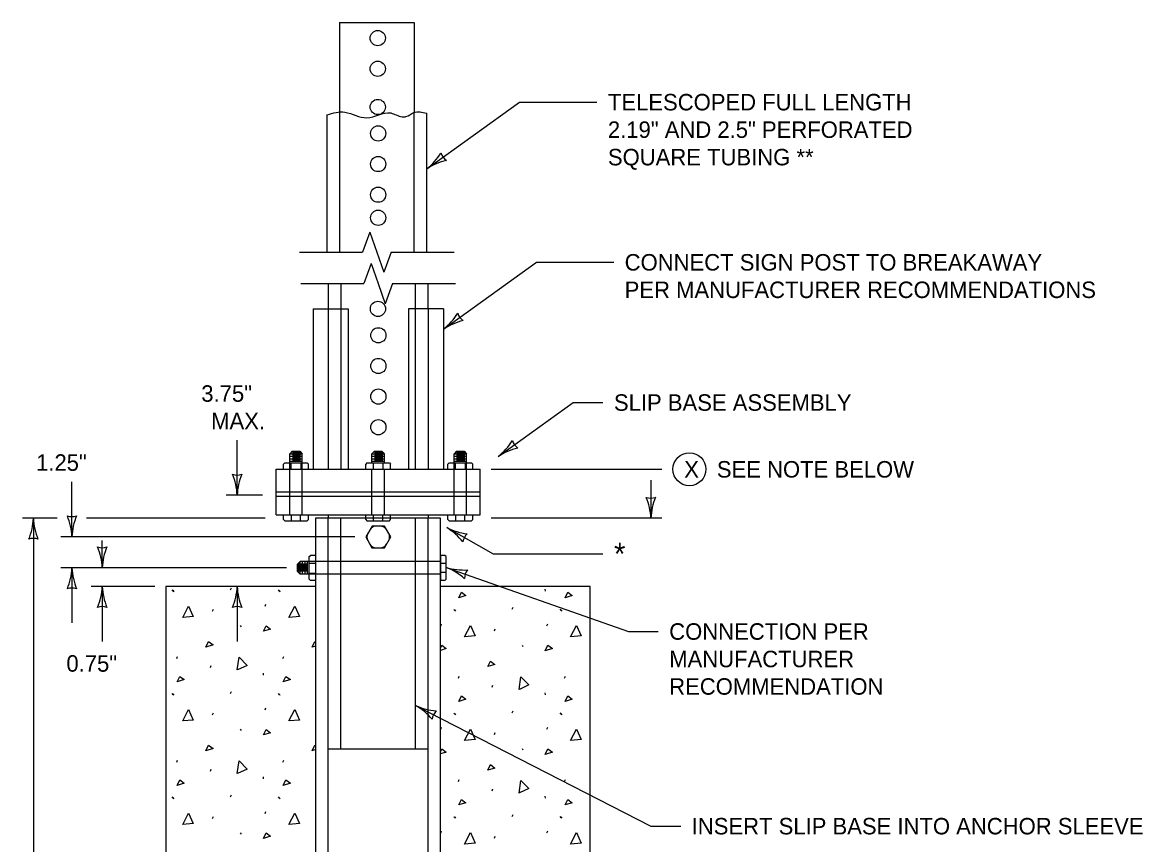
# Model space of a CAD drawing. Extents: x 49940 to 50043, y 49986 to 50011.
# Drawn here: x 49951.371 to 49955.45, y 49994.357 to 49997.349 of the extents above; entities that cross this region are included whole.
import ezdxf

# ---------------------------------------------------------------- set-up
doc = ezdxf.new("R2010")
doc.units = 0
for name, color, linetype in [('Level 1', 7, 'Continuous'), ('Level 2', 7, 'Continuous'), ('Level 3', 7, 'Continuous'), ('Level 4', 7, 'Continuous'), ('Level 6', 7, 'Continuous')]:
    doc.layers.add(name, color=color, linetype=linetype)

msp = doc.modelspace()

# ---------------------------------------------------------------- linework, layer by layer
at = {"layer": 'Level 1'}
for p, q in [((49952.5255, 49997.3494), (49952.798, 49997.3494)), ((49952.4305, 49996.3076), (49952.4305, 49995.7231)), ((49952.4305, 49996.3076), (49952.5577, 49996.3076)), ((49952.5577, 49996.3076), (49952.5577, 49995.7231)), ((49952.7772, 49996.3076), (49952.7772, 49995.7231)), ((49952.9044, 49996.3076), (49952.7772, 49996.3076)), ((49952.9044, 49996.3076), (49952.9044, 49995.7231)), ((49952.3541, 49995.7888), (49952.345, 49995.7798)), ((49952.345, 49995.7466), (49952.345, 49995.7798)), ((49952.345, 49995.7798), (49952.3904, 49995.7798)), ((49952.3541, 49995.7888), (49952.3813, 49995.7888)), ((49952.3542, 49995.7844), (49952.3841, 49995.7844)), ((49952.3542, 49995.7753), (49952.3841, 49995.7753)), ((49952.3813, 49995.7888), (49952.3904, 49995.7798)), ((49952.3904, 49995.7466), (49952.3904, 49995.7798)), ((49952.6531, 49995.7888), (49952.644, 49995.7798)), ((49952.644, 49995.7466), (49952.644, 49995.7798)), ((49952.644, 49995.7798), (49952.6895, 49995.7798)), ((49952.6531, 49995.7888), (49952.6804, 49995.7888)), ((49952.6533, 49995.7844), (49952.6832, 49995.7844)), ((49952.6533, 49995.7753), (49952.6832, 49995.7753)), ((49952.6804, 49995.7888), (49952.6895, 49995.7798)), ((49952.6895, 49995.7466), (49952.6895, 49995.7798)), ((49952.9522, 49995.7888), (49952.9431, 49995.7798)), ((49952.9431, 49995.7466), (49952.9431, 49995.7798)), ((49952.9431, 49995.7798), (49952.9885, 49995.7798)), ((49952.9522, 49995.7888), (49952.9794, 49995.7888)), ((49952.9523, 49995.7844), (49952.9822, 49995.7844)), ((49952.9523, 49995.7753), (49952.9822, 49995.7753)), ((49952.9794, 49995.7888), (49952.9885, 49995.7798)), ((49952.9885, 49995.7466), (49952.9885, 49995.7798)), ((49952.3267, 49995.7466), (49952.3223, 49995.742)), ((49952.3223, 49995.7231), (49952.3223, 49995.742)), ((49952.3267, 49995.7466), (49952.4086, 49995.7466)), ((49952.345, 49995.7708), (49952.3904, 49995.7708)), ((49952.345, 49995.7616), (49952.3904, 49995.7616)), ((49952.345, 49995.7526), (49952.3904, 49995.7526)), ((49952.3489, 49995.7466), (49952.3489, 49995.7242)), ((49952.3542, 49995.7662), (49952.3841, 49995.7662)), ((49952.3542, 49995.7571), (49952.3841, 49995.7571)), ((49952.3851, 49995.7466), (49952.3851, 49995.7242)), ((49952.4086, 49995.7466), (49952.4132, 49995.742)), ((49952.4132, 49995.7231), (49952.4132, 49995.742)), ((49952.6258, 49995.7466), (49952.6212, 49995.742)), ((49952.6212, 49995.7231), (49952.6212, 49995.742)), ((49952.6258, 49995.7466), (49952.7076, 49995.7466)), ((49952.644, 49995.7708), (49952.6895, 49995.7708)), ((49952.644, 49995.7616), (49952.6895, 49995.7616)), ((49952.644, 49995.7526), (49952.6895, 49995.7526)), ((49952.6481, 49995.7466), (49952.6481, 49995.7242)), ((49952.6533, 49995.7662), (49952.6832, 49995.7662)), ((49952.6533, 49995.7571), (49952.6832, 49995.7571)), ((49952.6841, 49995.7466), (49952.6841, 49995.7242)), ((49952.7076, 49995.7466), (49952.7121, 49995.742)), ((49952.7121, 49995.7231), (49952.7121, 49995.742)), ((49952.9249, 49995.7466), (49952.9203, 49995.742)), ((49952.9203, 49995.7231), (49952.9203, 49995.742)), ((49952.9249, 49995.7466), (49953.0067, 49995.7466)), ((49952.9431, 49995.7708), (49952.9885, 49995.7708)), ((49952.9431, 49995.7616), (49952.9885, 49995.7616)), ((49952.9431, 49995.7526), (49952.9885, 49995.7526)), ((49952.947, 49995.7466), (49952.947, 49995.7242)), ((49952.9523, 49995.7662), (49952.9822, 49995.7662)), ((49952.9523, 49995.7571), (49952.9822, 49995.7571)), ((49952.9832, 49995.7466), (49952.9832, 49995.7242)), ((49953.0067, 49995.7466), (49953.0112, 49995.742)), ((49953.0112, 49995.7231), (49953.0112, 49995.742)), ((49952.295, 49995.5571), (49952.295, 49995.7231)), ((49952.295, 49995.7231), (49952.644, 49995.7231)), ((49952.644, 49995.5571), (49952.644, 49995.7231)), ((49952.644, 49995.7231), (49952.6895, 49995.7231)), ((49952.6895, 49995.5571), (49952.6895, 49995.7231)), ((49952.6895, 49995.7231), (49953.0385, 49995.7231)), ((49953.0385, 49995.5571), (49953.0385, 49995.7231)), ((49952.295, 49995.6406), (49953.0385, 49995.6406)), ((49952.295, 49995.6257), (49953.0385, 49995.6257)), ((49952.295, 49995.5571), (49952.644, 49995.5571)), ((49952.3223, 49995.5404), (49952.3223, 49995.5571)), ((49952.3223, 49995.5404), (49952.3267, 49995.536)), ((49952.3267, 49995.536), (49952.4086, 49995.536)), ((49952.351, 49995.536), (49952.351, 49995.5566)), ((49952.3841, 49995.536), (49952.3841, 49995.5566)), ((49952.4086, 49995.536), (49952.4132, 49995.5404)), ((49952.4132, 49995.5404), (49952.4132, 49995.5571)), ((49952.4851, 49995.5571), (49952.4851, 49995.5448)), ((49952.6212, 49995.5404), (49952.6212, 49995.5571)), ((49952.6212, 49995.5404), (49952.6258, 49995.536)), ((49952.6258, 49995.536), (49952.7076, 49995.536)), ((49952.644, 49995.5571), (49952.6895, 49995.5571)), ((49952.6501, 49995.536), (49952.6501, 49995.5566)), ((49952.6832, 49995.536), (49952.6832, 49995.5566)), ((49952.6895, 49995.5571), (49953.0385, 49995.5571)), ((49952.7076, 49995.536), (49952.7121, 49995.5404)), ((49952.7121, 49995.5404), (49952.7121, 49995.5571)), ((49952.8484, 49995.5571), (49952.8484, 49995.5448)), ((49952.9203, 49995.5404), (49952.9203, 49995.5571)), ((49952.9203, 49995.5404), (49952.9249, 49995.536)), ((49952.9249, 49995.536), (49953.0067, 49995.536)), ((49952.9491, 49995.536), (49952.9491, 49995.5566)), ((49952.9822, 49995.536), (49952.9822, 49995.5566)), ((49953.0067, 49995.536), (49953.0112, 49995.5404)), ((49953.0112, 49995.5404), (49953.0112, 49995.5571)), ((49952.4154, 49995.4054), (49952.4201, 49995.41)), ((49952.4154, 49995.3236), (49952.4154, 49995.4054)), ((49952.439, 49995.41), (49952.4201, 49995.41)), ((49952.91, 49995.41), (49952.8933, 49995.41)), ((49952.8933, 49995.41), (49952.8933, 49995.319)), ((49952.9146, 49995.4054), (49952.91, 49995.41)), ((49952.9146, 49995.3236), (49952.9146, 49995.4054)), ((49952.3731, 49995.3782), (49952.3822, 49995.3872)), ((49952.3731, 49995.3508), (49952.3731, 49995.3782)), ((49952.3777, 49995.3511), (49952.3777, 49995.3809)), ((49952.4154, 49995.3872), (49952.3822, 49995.3872)), ((49952.3822, 49995.3418), (49952.3822, 49995.3872)), ((49952.3867, 49995.3511), (49952.3867, 49995.3809)), ((49952.3913, 49995.3418), (49952.3913, 49995.3872)), ((49952.3959, 49995.3511), (49952.3959, 49995.3809)), ((49952.4004, 49995.3418), (49952.4004, 49995.3872)), ((49952.4051, 49995.3511), (49952.4051, 49995.3809)), ((49952.4095, 49995.3418), (49952.4095, 49995.3872)), ((49952.4154, 49995.382), (49952.439, 49995.382)), ((49952.9146, 49995.3809), (49952.8939, 49995.3809)), ((49952.3731, 49995.3508), (49952.3822, 49995.3418)), ((49952.4154, 49995.3418), (49952.3822, 49995.3418)), ((49952.4154, 49995.3457), (49952.439, 49995.3457)), ((49952.9146, 49995.3478), (49952.8939, 49995.3478)), ((49952.439, 49995.2968), (49951.8937, 49995.2968)), ((49951.8937, 49995.2968), (49951.8937, 49992.5705)), ((49951.916, 49995.2847), (49951.9193, 49995.2798)), ((49952.129, 49995.2847), (49952.1323, 49995.292)), ((49952.3025, 49995.2847), (49952.3059, 49995.2798)), ((49952.4154, 49995.3236), (49952.4201, 49995.319)), ((49952.439, 49995.319), (49952.4201, 49995.319)), ((49952.91, 49995.319), (49952.8933, 49995.319)), ((49953.4386, 49995.2968), (49952.8933, 49995.2968)), ((49952.91, 49995.319), (49952.9146, 49995.3236)), ((49953.2735, 49995.287), (49953.2742, 49995.2798)), ((49953.4386, 49992.5705), (49953.4386, 49995.2968)), ((49951.9193, 49995.2828), (49951.9226, 49995.2778)), ((49952.3059, 49995.2828), (49952.3091, 49995.2778)), ((49952.0637, 49995.2063), (49952.067, 49995.2136)), ((49952.2549, 49995.2248), (49952.2582, 49995.2321)), ((49952.942, 49995.2138), (49952.9452, 49995.2088)), ((49952.9452, 49995.212), (49952.9484, 49995.207)), ((49953.155, 49995.2138), (49953.1583, 49995.221)), ((49953.3285, 49995.2138), (49953.3317, 49995.2088)), ((49953.3317, 49995.212), (49953.335, 49995.207)), ((49952.8945, 49995.1539), (49952.8975, 49995.1612)), ((49953.2808, 49995.1539), (49953.2841, 49995.1612)), ((49952.1647, 49995.1545), (49952.1679, 49995.1497)), ((49953.0897, 49995.1352), (49953.0928, 49995.1426)), ((49953.1906, 49995.0837), (49953.1937, 49995.0788)), ((49951.933, 49995.0343), (49951.9362, 49995.0416)), ((49952.3195, 49995.0343), (49952.3228, 49995.0416)), ((49952.0557, 49995.0013), (49952.0588, 49995.0086)), ((49952.2475, 49994.981), (49952.2482, 49994.9737)), ((49952.959, 49994.9634), (49952.9622, 49994.9707)), ((49953.3455, 49994.9634), (49953.3488, 49994.9707)), ((49953.0816, 49994.9303), (49953.0847, 49994.9375)), ((49951.916, 49994.9077), (49951.9193, 49994.9027)), ((49951.9193, 49994.9059), (49951.9226, 49994.901)), ((49952.129, 49994.9077), (49952.1323, 49994.9149)), ((49952.3025, 49994.9077), (49952.3059, 49994.9027)), ((49952.3059, 49994.9059), (49952.3091, 49994.901)), ((49953.2735, 49994.9101), (49953.2742, 49994.9027)), ((49952.0637, 49994.8293), (49952.067, 49994.8366)), ((49952.2549, 49994.8478), (49952.2582, 49994.8551)), ((49952.942, 49994.8366), (49952.9452, 49994.8319)), ((49952.9452, 49994.8348), (49952.9484, 49994.83)), ((49953.155, 49994.8366), (49953.1583, 49994.8441)), ((49953.3285, 49994.8366), (49953.3317, 49994.8319)), ((49953.3317, 49994.8348), (49953.335, 49994.83)), ((49952.1647, 49994.7776), (49952.1679, 49994.7728)), ((49952.8945, 49994.7769), (49952.8975, 49994.7842)), ((49953.0897, 49994.7584), (49953.0928, 49994.7656)), ((49953.2808, 49994.7769), (49953.2841, 49994.7842)), ((49953.1906, 49994.7067), (49953.1937, 49994.7018)), ((49951.933, 49994.6573), (49951.9362, 49994.6646)), ((49952.0557, 49994.6242), (49952.0588, 49994.6316)), ((49952.3195, 49994.6573), (49952.3228, 49994.6646)), ((49952.2475, 49994.604), (49952.2482, 49994.5967)), ((49952.959, 49994.5864), (49952.9622, 49994.5937)), ((49953.3455, 49994.5864), (49953.3488, 49994.5937)), ((49953.0816, 49994.5534), (49953.0847, 49994.5606)), ((49951.916, 49994.5306), (49951.9193, 49994.5259)), ((49951.9193, 49994.5288), (49951.9226, 49994.5241)), ((49952.129, 49994.5306), (49952.1323, 49994.538)), ((49952.3025, 49994.5306), (49952.3059, 49994.5259)), ((49952.3059, 49994.5288), (49952.3091, 49994.5241)), ((49953.2735, 49994.5333), (49953.2742, 49994.5259)), ((49952.2549, 49994.4709), (49952.2582, 49994.4781)), ((49952.0637, 49994.4523), (49952.067, 49994.4596)), ((49952.942, 49994.4598), (49952.9452, 49994.4549)), ((49952.9452, 49994.4579), (49952.9484, 49994.4531)), ((49953.155, 49994.4598), (49953.1583, 49994.467)), ((49953.3285, 49994.4598), (49953.3317, 49994.4549)), ((49953.3317, 49994.4579), (49953.335, 49994.4531)), ((49952.1647, 49994.4007), (49952.1679, 49994.3958)), ((49952.8945, 49994.3999), (49952.8975, 49994.4072)), ((49953.0897, 49994.3813), (49953.0928, 49994.3886)), ((49953.2808, 49994.3999), (49953.2841, 49994.4072))]:
    msp.add_line(p, q, dxfattribs=at)
for points in [[(49952.5255, 49997.3494), (49952.5255, 49997.02)], [(49952.798, 49997.3494), (49952.7981, 49997.0215)], [(49952.4801, 49997.0145), (49952.4803, 49996.5136)], [(49952.8434, 49996.5137), (49952.8434, 49997.0186)], [(49952.4851, 49996.3989), (49952.4851, 49996.3076)], [(49952.8483, 49996.3076), (49952.8483, 49996.3989)], [(49952.8933, 49992.7115), (49952.8933, 49995.5448), (49952.439, 49995.5448), (49952.439, 49992.7115)], [(49952.9605, 49995.2556), (49952.9701, 49995.2758), (49952.9864, 49995.2636), (49952.9605, 49995.2556)], [(49953.3471, 49995.2556), (49953.3568, 49995.2758), (49953.3729, 49995.2636), (49953.3471, 49995.2556)], [(49951.9549, 49995.1844), (49951.9766, 49995.2256), (49951.9936, 49995.1876), (49951.9556, 49995.1844)], [(49952.3413, 49995.1844), (49952.3632, 49995.2256), (49952.38, 49995.1876), (49952.3421, 49995.1844)], [(49952.2493, 49995.1336), (49952.259, 49995.1538), (49952.2751, 49995.1417), (49952.2493, 49995.1336)], [(49952.9807, 49995.1136), (49953.0025, 49995.1546), (49953.0194, 49995.1167), (49952.9814, 49995.1136)], [(49953.3673, 49995.1136), (49953.3891, 49995.1546), (49953.406, 49995.1167), (49953.3681, 49995.1136)], [(49952.0396, 49995.0759), (49952.0494, 49995.0959), (49952.0655, 49995.0839), (49952.0396, 49995.0759)], [(49952.4263, 49995.0759), (49952.4359, 49995.0959), (49952.439, 49995.0938)], [(49952.439, 49995.0798), (49952.4263, 49995.0759)], [(49952.8933, 49995.0724), (49952.8983, 49995.0829), (49952.9145, 49995.0707), (49952.8933, 49995.0642)], [(49953.2753, 49995.0628), (49953.2849, 49995.0829), (49953.3011, 49995.0707), (49953.2753, 49995.0628)], [(49952.1538, 49994.993), (49952.1603, 49995.0391), (49952.1891, 49995.0092), (49952.1546, 49994.9932)], [(49953.0656, 49995.005), (49953.0753, 49995.0252), (49953.0914, 49995.013), (49953.0656, 49995.005)], [(49951.9346, 49994.9496), (49951.9443, 49994.9697), (49951.9604, 49994.9577), (49951.9346, 49994.9496)], [(49952.3212, 49994.9496), (49952.331, 49994.9697), (49952.3469, 49994.9577), (49952.3212, 49994.9496)], [(49953.1798, 49994.922), (49953.1862, 49994.968), (49953.2151, 49994.9384), (49953.1807, 49994.9222)], [(49952.9605, 49994.8787), (49952.9701, 49994.8989), (49952.9864, 49994.8867), (49952.9605, 49994.8787)], [(49953.3471, 49994.8787), (49953.3568, 49994.8989), (49953.3729, 49994.8867), (49953.3471, 49994.8787)], [(49951.9549, 49994.8075), (49951.9766, 49994.8486), (49951.9936, 49994.8107), (49951.9556, 49994.8075)], [(49952.3413, 49994.8075), (49952.3632, 49994.8486), (49952.38, 49994.8107), (49952.3421, 49994.8075)], [(49952.2493, 49994.7566), (49952.259, 49994.7767), (49952.2751, 49994.7647), (49952.2493, 49994.7566)], [(49952.9807, 49994.7366), (49953.0025, 49994.7778), (49953.0194, 49994.7397), (49952.9814, 49994.7366)], [(49953.3673, 49994.7366), (49953.3891, 49994.7778), (49953.406, 49994.7397), (49953.3681, 49994.7366)], [(49952.0396, 49994.6989), (49952.0494, 49994.7191), (49952.0655, 49994.707), (49952.0396, 49994.6989)], [(49952.4263, 49994.6989), (49952.4359, 49994.7191), (49952.439, 49994.7168)], [(49952.439, 49994.7029), (49952.4263, 49994.6989)], [(49952.8933, 49994.6954), (49952.8983, 49994.7059), (49952.9145, 49994.6938), (49952.8933, 49994.6872)], [(49953.2753, 49994.6857), (49953.2849, 49994.7059), (49953.3011, 49994.6938), (49953.2753, 49994.6857)], [(49952.1538, 49994.6159), (49952.1603, 49994.662), (49952.1891, 49994.6322), (49952.1546, 49994.6163)], [(49953.0656, 49994.628), (49953.0753, 49994.6483), (49953.0914, 49994.6361), (49953.0656, 49994.628)], [(49951.9346, 49994.5726), (49951.9443, 49994.5928), (49951.9604, 49994.5807), (49951.9346, 49994.5726)], [(49952.3212, 49994.5726), (49952.331, 49994.5928), (49952.3469, 49994.5807), (49952.3212, 49994.5726)], [(49953.1798, 49994.545), (49953.1862, 49994.5911), (49953.2151, 49994.5613), (49953.1807, 49994.5453)], [(49952.9605, 49994.5018), (49952.9701, 49994.5218), (49952.9864, 49994.5098), (49952.9605, 49994.5018)], [(49953.3471, 49994.5018), (49953.3568, 49994.5218), (49953.3729, 49994.5098), (49953.3471, 49994.5018)], [(49951.9549, 49994.4306), (49951.9766, 49994.4717), (49951.9936, 49994.4337), (49951.9556, 49994.4306)], [(49952.3413, 49994.4306), (49952.3632, 49994.4717), (49952.38, 49994.4337), (49952.3421, 49994.4306)], [(49952.2493, 49994.3796), (49952.259, 49994.3999), (49952.2751, 49994.3879), (49952.2493, 49994.3796)], [(49952.9807, 49994.3595), (49953.0025, 49994.4009), (49953.0194, 49994.3628), (49952.9814, 49994.3595)], [(49953.3673, 49994.3595), (49953.3891, 49994.4009), (49953.406, 49994.3628), (49953.3681, 49994.3595)]]:
    msp.add_lwpolyline(points, dxfattribs=at)
msp.add_lwpolyline([(49952.6212, 49995.4772), (49952.644, 49995.4375), (49952.6896, 49995.4373), (49952.7128, 49995.4768), (49952.69, 49995.5164), (49952.6444, 49995.5167)], close=True, dxfattribs=at)
for centre in [(49952.6651, 49997.2924), (49952.6651, 49997.2924), (49952.6651, 49997.1808), (49952.6651, 49997.0416), (49952.6667, 49996.9455), (49952.6667, 49996.9455), (49952.6667, 49996.834), (49952.6667, 49996.834), (49952.6667, 49996.7224), (49952.6667, 49996.6386), (49952.6659, 49996.3068), (49952.6674, 49996.2108), (49952.6674, 49996.2108), (49952.6674, 49996.0992), (49952.6674, 49996.0992), (49952.6674, 49996.0992), (49952.6674, 49995.9877), (49952.6674, 49995.8761)]:
    msp.add_circle(centre, 0.0277, dxfattribs=at)
for centre, start, end in [((49952.6528, 49995.477), 149.6985, 209.6957), ((49952.6599, 49995.4893), 89.696, 149.6971), ((49952.6741, 49995.4892), 29.6985, 89.6961), ((49952.6812, 49995.4769), 329.6973, 29.6966), ((49952.6598, 49995.4647), 209.697, 269.6988), ((49952.674, 49995.4646), 269.6962, 329.6979)]:
    msp.add_arc(centre, 0.0273, start, end, dxfattribs=at)
msp.add_spline([(49952.4808, 49997.0137), (49952.5456, 49997.0228), (49952.6253, 49997.0023), (49952.7125, 49997.0198), (49952.7536, 49997.0059), (49952.7679, 49997.0065), (49952.7966, 49997.0216), (49952.8433, 49997.0186)], degree=3, dxfattribs=at)
at = {"layer": 'Level 2'}
msp.add_circle((49953.7999, 49995.7231), 0.06, dxfattribs=at)
at = {"layer": 'Level 3'}
for p, q in [((49952.8434, 49996.8162), (49953.1819, 49997.0592)), ((49953.1819, 49997.0592), (49953.4632, 49997.0592)), ((49952.9044, 49996.2334), (49953.2429, 49996.4764)), ((49953.2429, 49996.4764), (49953.5242, 49996.4764)), ((49953.1035, 49995.7697), (49953.377, 49995.9661)), ((49953.377, 49995.9661), (49953.4852, 49995.9661)), ((49952.1533, 49995.6289), (49952.1533, 49995.8289)), ((49953.0785, 49995.7231), (49953.6999, 49995.7231)), ((49951.5517, 49995.4777), (49951.5517, 49995.6777)), ((49953.6599, 49995.6831), (49953.6599, 49995.5448)), ((49952.2455, 49995.6289), (49952.1133, 49995.6289)), ((49951.4983, 49995.5448), (49951.3713, 49995.5448)), ((49951.4113, 49995.5448), (49951.4113, 49992.7115)), ((49952.255, 49995.5448), (49951.605, 49995.5448)), ((49953.6999, 49995.5448), (49953.0785, 49995.5448)), ((49952.9165, 49995.5108), (49953.0858, 49995.4159)), ((49952.5812, 49995.4772), (49951.5117, 49995.4772)), ((49951.6621, 49995.3645), (49951.6621, 49995.4638)), ((49953.0858, 49995.4159), (49953.4852, 49995.4159)), ((49952.9146, 49995.3662), (49953.5782, 49995.1328)), ((49952.3331, 49995.3645), (49951.5117, 49995.3645)), ((49951.5517, 49995.3645), (49951.5517, 49995.1645)), ((49951.8537, 49995.2968), (49951.6221, 49995.2968)), ((49951.6621, 49995.2968), (49951.6621, 49995.0968)), ((49952.1533, 49995.2968), (49952.1533, 49995.0968)), ((49953.5782, 49995.1328), (49953.6864, 49995.1328)), ((49952.8029, 49994.8636), (49953.6601, 49994.4244)), ((49953.6601, 49994.4244), (49953.7683, 49994.4244))]:
    msp.add_line(p, q, dxfattribs=at)
for centre, radius, start, end in [((49952.6984, 49996.9986), 0.233, 308.5009, 327.7507), ((49952.9476, 49996.891), 0.0548, 197.8124, 233.5347), ((49952.9655, 49996.6304), 0.2223, 103.1296, 123.3131), ((49952.7594, 49996.4157), 0.233, 308.5009, 327.7507), ((49953.0265, 49996.0476), 0.2223, 103.1296, 123.3131), ((49953.0086, 49996.3081), 0.0548, 197.8124, 233.5347), ((49952.9584, 49995.952), 0.233, 308.5094, 327.7592), ((49953.2076, 49995.8445), 0.0548, 197.8209, 233.5433), ((49953.2256, 49995.5839), 0.2223, 103.1381, 123.3216), ((49952.1533, 49995.7571), 0.0548, 252.1388, 287.8612), ((49951.9206, 49995.6174), 0.233, 2.8273, 22.0772), ((49952.3754, 49995.6198), 0.2223, 157.456, 177.6395), ((49953.6596, 49995.6732), 0.0548, 252.1388, 287.8612), ((49953.4269, 49995.5335), 0.233, 2.8273, 22.0772), ((49953.8818, 49995.5359), 0.2223, 157.456, 177.6395), ((49951.1892, 49995.554), 0.2223, 337.456, 357.6395), ((49951.644, 49995.5563), 0.233, 182.8273, 202.0772), ((49951.5517, 49995.6059), 0.0548, 252.1388, 287.8612), ((49951.319, 49995.4662), 0.233, 2.8273, 22.0772), ((49951.7738, 49995.4686), 0.2223, 157.456, 177.6395), ((49952.7999, 49995.3215), 0.2223, 38.1835, 58.367), ((49953.0203, 49995.7194), 0.233, 243.5548, 262.8046), ((49953.0283, 49995.4481), 0.0548, 132.8663, 168.5887), ((49951.4113, 49995.4166), 0.0548, 72.1388, 107.8612), ((49951.6621, 49995.4927), 0.0548, 252.1388, 287.8612), ((49951.4294, 49995.353), 0.233, 2.8273, 22.0772), ((49951.8842, 49995.3554), 0.2223, 157.456, 177.6395), ((49952.8323, 49995.1597), 0.2223, 48.0787, 68.2623), ((49952.981, 49995.5896), 0.233, 253.45, 272.6999), ((49951.3296, 49995.3737), 0.2223, 337.456, 357.6395), ((49951.7844, 49995.376), 0.233, 182.8273, 202.0772), ((49953.0356, 49995.3237), 0.0548, 142.7616, 178.4839), ((49951.5517, 49995.2363), 0.0548, 72.1388, 107.8612), ((49951.44, 49995.306), 0.2223, 337.456, 357.6395), ((49951.8948, 49995.3083), 0.233, 182.8273, 202.0772), ((49951.9312, 49995.306), 0.2223, 337.456, 357.6395), ((49952.386, 49995.3083), 0.233, 182.8273, 202.0772), ((49951.6621, 49995.1686), 0.0548, 72.1388, 107.8612), ((49952.1533, 49995.1686), 0.0548, 72.1388, 107.8612), ((49952.6935, 49994.6701), 0.2223, 40.3296, 60.5131), ((49952.8988, 49995.0759), 0.233, 245.7009, 264.9508), ((49952.917, 49994.8051), 0.0548, 135.0124, 170.7348)]:
    msp.add_arc(centre, radius, start, end, dxfattribs=at)
at = {"layer": 'Level 4'}
for p, q in [((49952.345, 49995.5571), (49952.345, 49995.7466)), ((49952.3904, 49995.5571), (49952.3904, 49995.7466)), ((49952.9431, 49995.5571), (49952.9431, 49995.7466)), ((49952.9885, 49995.5571), (49952.9885, 49995.7466)), ((49952.4851, 49992.7115), (49952.4851, 49995.5448)), ((49952.5304, 49994.7063), (49952.5304, 49995.5448)), ((49952.8029, 49994.7063), (49952.8029, 49995.5448)), ((49952.8484, 49992.7115), (49952.8484, 49995.5448)), ((49952.8933, 49995.3872), (49952.4154, 49995.3872)), ((49952.8933, 49995.3418), (49952.4154, 49995.3418)), ((49952.4851, 49994.7063), (49952.8484, 49994.7063))]:
    msp.add_line(p, q, dxfattribs=at)
for points in [[(49952.5255, 49997.02), (49952.5257, 49996.5136)], [(49952.7981, 49996.5137), (49952.7981, 49997.0215)], [(49952.5304, 49996.3989), (49952.5304, 49995.7231)], [(49952.8029, 49995.7231), (49952.8029, 49996.3989)], [(49952.4851, 49996.3076), (49952.4851, 49995.7231)], [(49952.8483, 49996.3076), (49952.8483, 49995.7231)]]:
    msp.add_lwpolyline(points, dxfattribs=at)
at = {"layer": 'Level 6'}
for p, q in [((49952.6359, 49996.5867), (49952.61, 49996.5136)), ((49952.6359, 49996.5867), (49952.6618, 49996.5136)), ((49952.3804, 49996.5136), (49952.61, 49996.5136)), ((49952.6618, 49996.5136), (49952.6877, 49996.4405)), ((49952.7136, 49996.5136), (49952.6877, 49996.4405)), ((49952.7136, 49996.5137), (49952.9433, 49996.5137)), ((49952.6408, 49996.472), (49952.6149, 49996.3989)), ((49952.6408, 49996.472), (49952.6667, 49996.3989)), ((49952.3851, 49996.3989), (49952.6149, 49996.3989)), ((49952.6667, 49996.3989), (49952.6926, 49996.3258)), ((49952.7185, 49996.3989), (49952.6926, 49996.3258)), ((49952.7185, 49996.3989), (49952.9483, 49996.3989))]:
    msp.add_line(p, q, dxfattribs=at)

# ---------------------------------------------------------------- texts
at = {"layer": 'Level 2'}
for s, p in [('TELESCOPED FULL LENGTH', (49953.5032, 49997.0292)), ('2.19" AND 2.5" PERFORATED', (49953.5032, 49996.9292)), ('SQUARE TUBING **', (49953.5032, 49996.8292)), ('CONNECT SIGN POST TO BREAKAWAY ', (49953.5642, 49996.4464)), ('PER MANUFACTURER RECOMMENDATIONS', (49953.5642, 49996.3464)), ('3.75"', (49952.0227, 49995.9689)), ('SLIP BASE ASSEMBLY', (49953.5252, 49995.9361)), ('MAX.', (49952.0585, 49995.8689)), ('1.25"', (49951.4211, 49995.7177)), ('X', (49953.7811, 49995.6931)), ('SEE NOTE BELOW', (49953.8999, 49995.6931)), ('CONNECTION PER ', (49953.7264, 49995.1028)), ('0.75"', (49951.5315, 49994.9866)), ('MANUFACTURER ', (49953.7264, 49995.0028)), ('RECOMMENDATION', (49953.7264, 49994.9028)), ('INSERT SLIP BASE INTO ANCHOR SLEEVE ', (49953.8083, 49994.3944))]:
    msp.add_text(s, height=0.06, dxfattribs=at).set_placement(p)
msp.add_text('*', height=0.08, rotation=359.5, dxfattribs=at).set_placement((49953.5249, 49995.3759))

doc.saveas('drawing.dxf')
